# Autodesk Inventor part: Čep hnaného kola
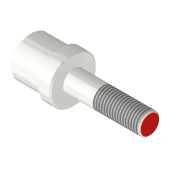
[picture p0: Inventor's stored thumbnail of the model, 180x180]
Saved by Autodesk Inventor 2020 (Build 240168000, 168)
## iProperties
Created: 2025-03
Part Number: Čep hnaného kola
Material: Ocel
Document SubType Name: Modeling
Designer: doma
Density: 7.85 g/cm^3
Appearance: Ocel
Mass: 286.049 g
Surface Area: 83.5112 cm^2
Volume: 36.4394 cm^3
Author: doma
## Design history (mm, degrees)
sketch "Náčrt1"
  geometry: L1 (11.525, 0)-(11.525, 8); L2 (11.525, 8)-(-45.675, 8); L3 (-45.675, 8)-(-45.675, 17.5); L4 (-45.675, 17.5)-(-54.675, 17.5); L5 (-54.675, 17.5)-(-54.675, 15); L6 (-54.675, 15)-(-78.475, 15); L7 (-78.475, 15)-(-78.475, 0); L8 (11.525, 0)-(-78.475, 0); 1 further point
  constraints: 16 end point, 4 perpendicular, 3 vertical, 1 horizontal, 1 point on line
  dimensions: "d0" = 8 distance of L1.start L1.end; "d5" = 9 distance of L3.end L4.end; "d6" = 23.8 distance of L5.end L6.end; "d7" = 17.5 distance between parallel lines of L8 L4; "d8" = 90 distance between parallel lines of L1 L7; "d9" = 15 distance of L6.end L7.end
revolve "Rotace1" sketch "Náčrt1" stored, may be unused: angle "d10" = 90 deg
feature "Závit1" dims "d11" = 35, "d12" = 0
sketch "Náčrt2"
  geometry: 1 further point
hole "Díra1" sketch "Náčrt2" at (0, 0) diameter "d13" = 6.647; stored, may be unused: countersink angle "d17" = 90 deg, drill point angle "d19" = 118 deg; dims "d14" = 10, "d15" = 4, "d16" = 2, "d18" = 15
chamfer "Zkosení1" distance "d20" = 1; stored, may be unused: second distance "d21" = 2, angle "d22" = 45 deg
fillet "Zaoblení1" dims "d23" = 0.2
fillet "Zaoblení2" dims "d30" = 0.2
node "Těleso1"
